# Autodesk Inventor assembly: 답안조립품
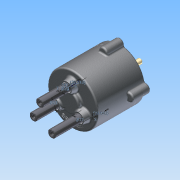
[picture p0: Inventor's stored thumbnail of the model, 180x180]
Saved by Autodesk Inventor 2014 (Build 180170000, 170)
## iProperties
Created: 2015-09
Part Number: 답안조립품
Document SubType Name: Assembly
Designer: study
Mass: 2160.25 g
Surface Area: 1801.24 cm^2
Volume: 438.523 cm^3
Density: 4.9262 g/cm^3
Author: study
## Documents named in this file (14)
- C:\Users\study\Desktop\350916V1022\답안조립품.iam
- C:\Users\study\Desktop\350916V1022\몸체.ipt
- C:\Users\study\Desktop\350916V1022\11-가변 스프링.ipt
- C:\Users\study\Desktop\350916V1022\12-가변 스프링.ipt
- C:\Users\study\Desktop\350916V1022\13-가변 스프링.ipt
- C:\Users\study\Desktop\350916V1022\멈춤링 10 x 1.ipt
- C:\Users\study\Desktop\350916V1022\메인 축.ipt
- C:\Users\study\Desktop\350916V1022\오일실.ipt
- C:\Users\study\Desktop\350916V1022\커버.ipt
- C:\Users\study\Desktop\350916V1022\판캠.ipt
- C:\Users\study\Desktop\350916V1022\멈춤링 22 x 1.2.ipt
- C:\Users\study\Desktop\350916V1022\베어링 NA 4900.ipt
- C:\Users\study\Desktop\350916V1022\M5x0.8x20.ipt
- C:\Users\study\Desktop\350916V1022\슬라이드 축.ipt
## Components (7 placed, 4 different names)
1. 11-가변 스프링:1
2. 12-가변 스프링:1
3. 13-가변 스프링:1
4. M5x0.8x20:1
5. M5x0.8x20:2
6. M5x0.8x20:3
7. M5x0.8x20:4
